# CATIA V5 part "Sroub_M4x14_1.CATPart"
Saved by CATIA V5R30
Part number: Sroub_M4x14_1
Definition: 2025_05_12_09_08_15_0912
Nomenclature: 2025_05_12_09_08_15_0912
Source: Unknown
Description: PART--DESC
Bounding box of the stored display mesh (mm): x 5.5 to 12.5, y -1.99 to 4.99, z -5 to 9
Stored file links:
  E:\Bakalarka\Model\Forma_v7\Sroub_M4x14_1.CATPart
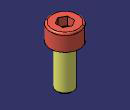
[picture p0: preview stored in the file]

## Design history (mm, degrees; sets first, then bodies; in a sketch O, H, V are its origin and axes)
Body1 "E2716_16B_NAUO4#E1200_4x10;Importiert1" (main body)
  Solid1: solid without history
